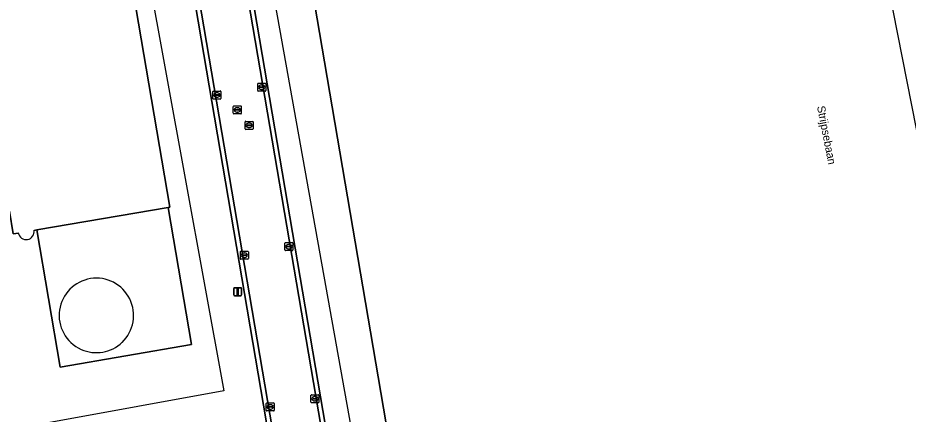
# Model space of a CAD drawing. Extents: x 154324 to 155744, y 382937 to 384188.
# Drawn here: x 154562 to 154673.2, y 383152.9 to 383202.4 of the extents above; entities that cross this region are included whole.
import ezdxf

# ---------------------------------------------------------------- set-up
doc = ezdxf.new("R2010")
doc.units = 0
for name, color, linetype in [('IMGEO_Bouwland', 7, 'Continuous'), ('IMGEO_Erf', 7, 'Continuous'), ('IMGEO_Kolk', 7, 'Continuous'), ('IMGEO_Lichtmast', 7, 'Continuous'), ('IMGEO_Openbare_ruimte_label', 7, 'Continuous'), ('IMGEO_Opslagtank', 7, 'Continuous'), ('IMGEO_Pand', 7, 'Continuous'), ('IMGEO_Pand_vergunning_verleend', 7, 'Continuous'), ('IMGEO_Rijbaan_lokaal_gesloten', 7, 'Continuous'), ('IMGEO_Rioolput', 7, 'Continuous')]:
    doc.layers.add(name, color=color, linetype=linetype)

msp = doc.modelspace()

# ---------------------------------------------------------------- linework, layer by layer
at = {"layer": 'IMGEO_Bouwland'}
for points in [[(154615.41, 383020.4), (154595.72, 383135.94), (154571.56, 383277.87), (154564.29, 383276.6), (154564.29, 383276.58), (154580.95, 383178.75), (154580.73, 383178.71), (154583.64, 383161.62), (154567.26, 383158.8), (154564.35, 383175.93)], [(154562.03, 383175.54), (154561.39, 383175.43), (154560.93, 383178.26), (154468.8, 383162.6), (154469.46, 383158.8), (154442.14, 383154.08), (154422.8, 383252.54), (154415.36, 383251.02), (154421.39, 383220.37), (154444.99, 383100.45), (154464.56, 383001.13), (154467.07, 382988.35)], [(154564.35, 383175.93), (154563.98, 383175.87)]]:
    msp.add_lwpolyline(points, dxfattribs=at)
msp.add_arc((154563, 383175.71), 0.992, 189.843, 9.4331, dxfattribs=at)
at = {"layer": 'IMGEO_Erf'}
msp.add_lwpolyline([(154639.96, 383035.6), (154623.69, 383130.92), (154616.87, 383129.76), (154616.83, 383129.75), (154616.71, 383130.48), (154612.74, 383129.8), (154612.11, 383133.49), (154611.26, 383133.35), (154609.37, 383144.42), (154609.22, 383144.4), (154590.4, 383254.85), (154588.66, 383265.07), (154600.5, 383267.08), (154598.69, 383277.78), (154579.44, 383274.33), (154619.76, 383037.83)], dxfattribs=at)
msp.add_lwpolyline([(154580.73, 383178.71), (154564.35, 383175.93), (154567.26, 383158.8), (154583.64, 383161.62)], close=True, dxfattribs=at)
for centre, radius, start, end in [((154571.77, 383165.25), 4.65, 313.6643, 171.6858), ((154571.77, 383165.26), 4.66, 171.7012, 245.8309), ((154571.77, 383165.26), 4.66, 245.8538, 313.6585)]:
    msp.add_arc(centre, radius, start, end, dxfattribs=at)
at = {"layer": 'IMGEO_Kolk'}
for p, q in [((154591.92, 383193.32), (154591.92, 383194.17)), ((154591.99, 383194.25), (154592.84, 383194.25)), ((154592.17, 383193.74), (154592.17, 383193.75)), ((154592.61, 383193.7), (154592.21, 383193.7)), ((154592.22, 383193.79), (154592.61, 383193.79)), ((154592.4, 383194.03), (154592.43, 383194.03)), ((154592.66, 383193.75), (154592.66, 383193.74)), ((154592.92, 383194.17), (154592.92, 383193.32)), ((154586.32, 383192.35), (154586.32, 383193.2)), ((154586.39, 383193.27), (154587.25, 383193.27)), ((154586.58, 383192.77), (154586.58, 383192.78)), ((154586.62, 383192.82), (154587.02, 383192.82)), ((154587.02, 383192.73), (154586.62, 383192.73)), ((154586.81, 383193.05), (154586.83, 383193.05)), ((154586.83, 383192.49), (154586.81, 383192.49)), ((154587.06, 383192.78), (154587.06, 383192.77)), ((154587.32, 383193.2), (154587.32, 383192.35)), ((154592.84, 383193.25), (154591.99, 383193.25)), ((154592.43, 383193.47), (154592.4, 383193.47)), ((154587.25, 383192.27), (154586.39, 383192.27)), ((154595.31, 383173.42), (154595.31, 383174.27)), ((154595.38, 383174.34), (154596.23, 383174.34)), ((154595.56, 383173.84), (154595.56, 383173.85)), ((154596, 383173.8), (154595.6, 383173.8)), ((154595.61, 383173.89), (154596, 383173.89)), ((154595.79, 383174.12), (154595.82, 383174.12)), ((154595.82, 383173.56), (154595.79, 383173.56)), ((154596.05, 383173.85), (154596.05, 383173.84)), ((154596.31, 383174.27), (154596.31, 383173.42)), ((154589.75, 383172.34), (154589.75, 383173.19)), ((154589.82, 383173.27), (154590.67, 383173.27)), ((154590, 383172.76), (154590, 383172.77)), ((154590.44, 383172.72), (154590.04, 383172.72)), ((154590.05, 383172.81), (154590.44, 383172.81)), ((154590.23, 383173.05), (154590.26, 383173.05)), ((154590.26, 383172.49), (154590.23, 383172.49)), ((154590.49, 383172.77), (154590.49, 383172.76)), ((154590.75, 383173.19), (154590.75, 383172.34)), ((154596.23, 383173.34), (154595.38, 383173.34)), ((154590.67, 383172.27), (154589.82, 383172.27)), ((154598.57, 383154.42), (154598.57, 383155.27)), ((154598.64, 383155.34), (154599.5, 383155.34)), ((154598.83, 383154.84), (154598.83, 383154.85)), ((154598.87, 383154.89), (154599.27, 383154.89)), ((154599.27, 383154.8), (154598.87, 383154.8)), ((154599.06, 383155.12), (154599.08, 383155.12)), ((154599.31, 383154.85), (154599.31, 383154.84)), ((154599.57, 383155.27), (154599.57, 383154.42)), ((154592.98, 383153.4), (154592.98, 383154.25)), ((154593.05, 383154.32), (154593.9, 383154.32)), ((154593.23, 383153.82), (154593.23, 383153.83)), ((154593.67, 383153.78), (154593.27, 383153.78)), ((154593.28, 383153.87), (154593.68, 383153.87)), ((154593.46, 383154.1), (154593.49, 383154.1)), ((154593.49, 383153.54), (154593.46, 383153.54)), ((154593.72, 383153.83), (154593.72, 383153.82)), ((154593.98, 383154.25), (154593.98, 383153.4)), ((154599.5, 383154.34), (154598.64, 383154.34)), ((154599.08, 383154.56), (154599.05, 383154.56)), ((154593.9, 383153.32), (154593.05, 383153.32))]:
    msp.add_line(p, q, dxfattribs=at)
for points in [[(154591.92, 383193.32), (154591.92, 383194.17)], [(154591.99, 383194.25), (154592.84, 383194.25)], [(154592.92, 383194.17), (154592.92, 383193.32)], [(154586.32, 383192.35), (154586.32, 383193.2)], [(154586.39, 383193.27), (154587.25, 383193.27)], [(154587.32, 383193.2), (154587.32, 383192.35)], [(154592.84, 383193.25), (154591.99, 383193.25)], [(154587.25, 383192.27), (154586.39, 383192.27)], [(154595.31, 383173.42), (154595.31, 383174.27)], [(154595.38, 383174.34), (154596.23, 383174.34)], [(154596.31, 383174.27), (154596.31, 383173.42)], [(154589.75, 383172.34), (154589.75, 383173.19)], [(154589.82, 383173.27), (154590.67, 383173.27)], [(154590.75, 383173.19), (154590.75, 383172.34)], [(154596.23, 383173.34), (154595.38, 383173.34)], [(154590.67, 383172.27), (154589.82, 383172.27)], [(154598.57, 383154.42), (154598.57, 383155.27)], [(154598.64, 383155.34), (154599.5, 383155.34)], [(154599.57, 383155.27), (154599.57, 383154.42)], [(154592.98, 383153.4), (154592.98, 383154.25)], [(154593.05, 383154.32), (154593.9, 383154.32)], [(154593.98, 383154.25), (154593.98, 383153.4)], [(154599.5, 383154.34), (154598.64, 383154.34)], [(154593.9, 383153.32), (154593.05, 383153.32)]]:
    msp.add_lwpolyline(points, dxfattribs=at)
for centre, radius, start, end in [((154591.99, 383194.17), 0.0765, 91.552, 178.448), ((154591.99, 383194.17), 0.0765, 91.552, 178.448), ((154592.21, 383193.75), 0.0403, 85.8775, 175.7526), ((154592.21, 383193.74), 0.0366, 178.938, 274.7102), ((154592.62, 383193.75), 0.0386, 1.7309, 96.639), ((154592.62, 383193.75), 0.043, 264.8664, 352.4533), ((154592.84, 383194.17), 0.0765, 1.552, 88.448), ((154592.84, 383194.17), 0.0765, 1.552, 88.448), ((154586.4, 383193.2), 0.0765, 91.552, 178.448), ((154586.4, 383193.2), 0.0765, 91.552, 178.448), ((154586.62, 383192.78), 0.0403, 85.8775, 175.7526), ((154586.62, 383192.77), 0.0366, 178.938, 274.7102), ((154587.02, 383192.78), 0.0386, 1.7309, 96.639), ((154587.02, 383192.77), 0.043, 264.8664, 352.4533), ((154587.24, 383193.2), 0.0765, 1.552, 88.448), ((154587.24, 383193.2), 0.0765, 1.552, 88.448), ((154591.99, 383193.32), 0.0765, 181.552, 268.448), ((154591.99, 383193.32), 0.0765, 181.552, 268.448), ((154592.84, 383193.32), 0.0765, 271.552, 358.448), ((154592.84, 383193.32), 0.0765, 271.552, 358.448), ((154586.4, 383192.35), 0.0765, 181.552, 268.448), ((154586.4, 383192.35), 0.0765, 181.552, 268.448), ((154587.24, 383192.35), 0.0765, 271.552, 358.448), ((154587.24, 383192.35), 0.0765, 271.552, 358.448), ((154595.38, 383174.27), 0.0765, 91.552, 178.448), ((154595.38, 383174.27), 0.0765, 91.552, 178.448), ((154595.6, 383173.85), 0.0403, 85.8775, 175.7526), ((154595.6, 383173.84), 0.0366, 178.938, 274.7102), ((154596.01, 383173.85), 0.0386, 1.7309, 96.639), ((154596.01, 383173.84), 0.043, 264.8664, 352.4533), ((154596.23, 383174.27), 0.0765, 1.552, 88.448), ((154596.23, 383174.27), 0.0765, 1.552, 88.448), ((154589.82, 383173.19), 0.0765, 91.552, 178.448), ((154589.82, 383173.19), 0.0765, 91.552, 178.448), ((154590.04, 383172.77), 0.0403, 85.8775, 175.7526), ((154590.04, 383172.76), 0.0366, 178.938, 274.7102), ((154590.45, 383172.77), 0.0386, 1.7309, 96.639), ((154590.45, 383172.77), 0.043, 264.8664, 352.4533), ((154590.67, 383173.19), 0.0765, 1.552, 88.448), ((154590.67, 383173.19), 0.0765, 1.552, 88.448), ((154595.38, 383173.42), 0.0765, 181.552, 268.448), ((154595.38, 383173.42), 0.0765, 181.552, 268.448), ((154596.23, 383173.42), 0.0765, 271.552, 358.448), ((154596.23, 383173.42), 0.0765, 271.552, 358.448), ((154589.82, 383172.34), 0.0765, 181.552, 268.448), ((154589.82, 383172.34), 0.0765, 181.552, 268.448), ((154590.67, 383172.34), 0.0765, 271.552, 358.448), ((154590.67, 383172.34), 0.0765, 271.552, 358.448), ((154598.65, 383155.27), 0.0765, 91.552, 178.448), ((154598.65, 383155.27), 0.0765, 91.552, 178.448), ((154598.87, 383154.85), 0.0403, 85.8775, 175.7526), ((154598.86, 383154.84), 0.0366, 178.938, 274.7102), ((154599.27, 383154.85), 0.0386, 1.7309, 96.639), ((154599.27, 383154.84), 0.043, 264.8664, 352.4533), ((154599.49, 383155.27), 0.0765, 1.552, 88.448), ((154599.49, 383155.27), 0.0765, 1.552, 88.448), ((154593.05, 383154.25), 0.0765, 91.552, 178.448), ((154593.05, 383154.25), 0.0765, 91.552, 178.448), ((154593.28, 383153.83), 0.0403, 85.8775, 175.7526), ((154593.27, 383153.82), 0.0366, 178.938, 274.7102), ((154593.68, 383153.82), 0.043, 264.8664, 352.4533), ((154593.68, 383153.83), 0.0386, 1.7309, 96.639), ((154593.9, 383154.25), 0.0765, 1.552, 88.448), ((154593.9, 383154.25), 0.0765, 1.552, 88.448), ((154598.65, 383154.42), 0.0765, 181.552, 268.448), ((154598.65, 383154.42), 0.0765, 181.552, 268.448), ((154599.49, 383154.42), 0.0765, 271.552, 358.448), ((154599.49, 383154.42), 0.0765, 271.552, 358.448), ((154593.05, 383153.4), 0.0765, 181.552, 268.448), ((154593.05, 383153.4), 0.0765, 181.552, 268.448), ((154593.9, 383153.4), 0.0765, 271.552, 358.448), ((154593.9, 383153.4), 0.0765, 271.552, 358.448)]:
    msp.add_arc(centre, radius, start, end, dxfattribs=at)
for centre, major_axis, ratio, start_param, end_param in [((154592.4, 383193.75), (-0.387, 0.002), 0.722429, 4.712389, 7.853982), ((154592.43, 383193.75), (-0.39, 0.002), 0.717154, 1.570796, 4.712389), ((154586.81, 383192.77), (-0.387, 0.002), 0.722429, 4.712389, 7.853982), ((154586.83, 383192.77), (-0.39, 0.002), 0.717154, 1.570796, 4.712389), ((154595.79, 383173.84), (-0.387, 0.002), 0.722429, 4.712389, 7.853982), ((154595.82, 383173.84), (-0.39, 0.002), 0.717154, 1.570796, 4.712389), ((154590.23, 383172.77), (-0.387, 0.002), 0.722429, 4.712389, 7.853982), ((154590.26, 383172.77), (-0.39, 0.002), 0.717154, 1.570796, 4.712389), ((154599.06, 383154.84), (-0.387, 0.002), 0.722429, 4.712389, 7.853982), ((154599.08, 383154.84), (-0.39, 0.002), 0.717154, 1.570796, 4.712389), ((154593.46, 383153.82), (-0.387, 0.002), 0.722429, 4.712389, 7.853982), ((154593.49, 383153.82), (-0.39, 0.002), 0.717154, 1.570796, 4.712389)]:
    msp.add_ellipse(centre, major_axis=major_axis, ratio=ratio, start_param=start_param, end_param=end_param, dxfattribs=at)
at = {"layer": 'IMGEO_Lichtmast'}
for p, q in [((154588.92, 383167.81), (154588.92, 383168.61)), ((154588.92, 383168.61), (154588.92, 383167.81)), ((154589.02, 383168.71), (154589.81, 383168.71)), ((154589.81, 383168.71), (154589.02, 383168.71)), ((154589.91, 383168.61), (154589.91, 383167.81)), ((154589.91, 383167.81), (154589.91, 383168.61)), ((154589.81, 383167.71), (154589.02, 383167.71)), ((154589.02, 383167.71), (154589.81, 383167.71))]:
    msp.add_line(p, q, dxfattribs=at)
msp.add_lwpolyline([(154589.34, 383168.58), (154589.49, 383168.58), (154589.49, 383167.83), (154589.34, 383167.83), (154589.34, 383168.58)], dxfattribs=at)
for centre, start, end in [((154589.02, 383168.61), 90, 180), ((154589.02, 383168.61), 90, 180), ((154589.81, 383168.61), 0, 90), ((154589.81, 383168.61), 360, 90), ((154589.02, 383167.81), 180, 270), ((154589.02, 383167.81), 180, 270), ((154589.81, 383167.81), 270, 0), ((154589.81, 383167.81), 270, 0)]:
    msp.add_arc(centre, 0.1, start, end, dxfattribs=at)
at = {"layer": 'IMGEO_Opslagtank'}
for centre, radius, start, end in [((154571.77, 383165.25), 4.65, 313.6643, 171.6858), ((154571.77, 383165.26), 4.66, 171.7012, 245.8309), ((154571.77, 383165.26), 4.66, 245.8538, 313.6585)]:
    msp.add_arc(centre, radius, start, end, dxfattribs=at)
at = {"layer": 'IMGEO_Pand'}
for points in [[(154700.96, 383055.6), (154678.39, 383188.11), (154676.25, 383200.68), (154676.1, 383201.52), (154675.85, 383203.03), (154675.73, 383203.72), (154663.13, 383277.68), (154662.98, 383277.66), (154600.5, 383267.08), (154588.66, 383265.07), (154590.4, 383254.85), (154609.22, 383144.4), (154609.37, 383144.42), (154611.26, 383133.35), (154612.11, 383133.49), (154612.74, 383129.8), (154616.71, 383130.48), (154616.83, 383129.75), (154616.87, 383129.76), (154623.69, 383130.92), (154639.96, 383035.6)], [(154564.29, 383276.58), (154422.8, 383252.54), (154442.14, 383154.08), (154469.46, 383158.8), (154468.8, 383162.6), (154560.93, 383178.26), (154561.39, 383175.43), (154562.03, 383175.54)], [(154563.98, 383175.87), (154564.35, 383175.93), (154580.73, 383178.71), (154580.95, 383178.75), (154564.29, 383276.58)]]:
    msp.add_lwpolyline(points, dxfattribs=at)
msp.add_arc((154563, 383175.71), 0.992, 189.843, 9.4331, dxfattribs=at)
at = {"layer": 'IMGEO_Pand_vergunning_verleend'}
for points in [[(154412.9, 383246.6), (154566.07, 383274.51), (154587.69, 383155.85), (154434.52, 383127.94)], [(154584.71, 383256.81), (154657.95, 383270.71), (154700.13, 383056.8), (154641.93, 383027.88), (154620.8, 383127.07), (154608.34, 383124.84)]]:
    msp.add_lwpolyline(points, close=True, dxfattribs=at)
at = {"layer": 'IMGEO_Rijbaan_lokaal_gesloten'}
for points in [[(154619.83, 383033.81), (154619.19, 383037.76), (154575.23, 383295.54), (154572.53, 383311.3), (154563.42, 383365.05), (154563.21, 383366.56)], [(154557.23, 383365.65), (154566.84, 383309.22), (154571.25, 383283.17), (154596.31, 383136.06), (154614.99, 383026.46)], [(154578.44, 383280.19), (154575.8, 383295.64), (154575.23, 383295.54), (154619.19, 383037.76), (154619.83, 383033.81)], [(154571.25, 383283.17), (154570.67, 383283.11), (154571.56, 383277.87), (154595.72, 383135.94), (154615.41, 383020.4)], [(154616, 383020.53), (154614.99, 383026.46), (154596.31, 383136.06), (154571.25, 383283.17)], [(154620.39, 383033.9), (154619.76, 383037.83), (154579.44, 383274.33), (154578.44, 383280.19)]]:
    msp.add_lwpolyline(points, dxfattribs=at)
at = {"layer": 'IMGEO_Rioolput'}
for p, q in [((154588.87, 383190.49), (154588.87, 383191.34)), ((154588.95, 383191.41), (154589.8, 383191.41)), ((154589.87, 383191.34), (154589.87, 383190.49)), ((154589.8, 383190.41), (154588.95, 383190.41)), ((154589.13, 383190.91), (154589.13, 383190.92)), ((154589.17, 383190.96), (154589.57, 383190.96)), ((154589.57, 383190.87), (154589.17, 383190.87)), ((154589.36, 383191.19), (154589.38, 383191.19)), ((154589.38, 383190.63), (154589.36, 383190.63)), ((154589.61, 383190.92), (154589.61, 383190.91)), ((154590.35, 383188.56), (154590.35, 383189.41)), ((154590.42, 383189.48), (154591.27, 383189.48)), ((154590.83, 383189.26), (154590.86, 383189.26)), ((154591.35, 383189.41), (154591.35, 383188.56)), ((154591.27, 383188.48), (154590.42, 383188.48)), ((154590.6, 383188.98), (154590.6, 383188.99)), ((154591.04, 383188.94), (154590.64, 383188.94)), ((154590.65, 383189.03), (154591.05, 383189.03)), ((154590.86, 383188.7), (154590.83, 383188.7)), ((154591.09, 383188.99), (154591.09, 383188.98))]:
    msp.add_line(p, q, dxfattribs=at)
for points in [[(154588.87, 383190.49), (154588.87, 383191.34)], [(154588.95, 383191.41), (154589.8, 383191.41)], [(154589.87, 383191.34), (154589.87, 383190.49)], [(154589.8, 383190.41), (154588.95, 383190.41)], [(154590.35, 383188.56), (154590.35, 383189.41)], [(154590.42, 383189.48), (154591.27, 383189.48)], [(154591.35, 383189.41), (154591.35, 383188.56)], [(154591.27, 383188.48), (154590.42, 383188.48)]]:
    msp.add_lwpolyline(points, dxfattribs=at)
for centre, radius, start, end in [((154588.95, 383191.34), 0.0765, 91.552, 178.448), ((154588.95, 383191.34), 0.0765, 91.552, 178.448), ((154589.8, 383191.34), 0.0765, 1.552, 88.448), ((154589.8, 383191.34), 0.0765, 1.552, 88.448), ((154588.95, 383190.49), 0.0765, 181.552, 268.448), ((154588.95, 383190.49), 0.0765, 181.552, 268.448), ((154589.17, 383190.92), 0.0403, 85.8775, 175.7526), ((154589.17, 383190.91), 0.0366, 178.938, 274.7102), ((154589.58, 383190.92), 0.0386, 1.7309, 96.639), ((154589.57, 383190.91), 0.043, 264.8664, 352.4533), ((154589.8, 383190.49), 0.0765, 271.552, 358.448), ((154589.8, 383190.49), 0.0765, 271.552, 358.448), ((154590.42, 383189.41), 0.0765, 91.552, 178.448), ((154590.42, 383189.41), 0.0765, 91.552, 178.448), ((154591.27, 383189.41), 0.0765, 1.552, 88.448), ((154591.27, 383189.41), 0.0765, 1.552, 88.448), ((154590.42, 383188.56), 0.0765, 181.552, 268.448), ((154590.42, 383188.56), 0.0765, 181.552, 268.448), ((154590.65, 383188.99), 0.0403, 85.8775, 175.7526), ((154590.64, 383188.98), 0.0366, 178.938, 274.7102), ((154591.05, 383188.98), 0.043, 264.8664, 352.4533), ((154591.05, 383188.99), 0.0386, 1.7309, 96.639), ((154591.27, 383188.56), 0.0765, 271.552, 358.448), ((154591.27, 383188.56), 0.0765, 271.552, 358.448)]:
    msp.add_arc(centre, radius, start, end, dxfattribs=at)
for centre, major_axis, ratio, start_param, end_param in [((154589.36, 383190.91), (-0.387, 0.002), 0.722429, 4.712389, 7.853982), ((154589.38, 383190.91), (-0.39, 0.002), 0.717154, 1.570796, 4.712389), ((154590.83, 383188.98), (-0.387, 0.002), 0.722429, 4.712389, 7.853982), ((154590.86, 383188.98), (-0.39, 0.002), 0.717154, 1.570796, 4.712389)]:
    msp.add_ellipse(centre, major_axis=major_axis, ratio=ratio, start_param=start_param, end_param=end_param, dxfattribs=at)

# ---------------------------------------------------------------- texts
at = {"layer": 'IMGEO_Openbare_ruimte_label'}
msp.add_text('Strijpsebaan', height=1, rotation=281.1301, dxfattribs=at).set_placement((154661.76, 383191.32))

doc.saveas('drawing.dxf')
